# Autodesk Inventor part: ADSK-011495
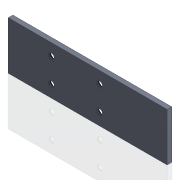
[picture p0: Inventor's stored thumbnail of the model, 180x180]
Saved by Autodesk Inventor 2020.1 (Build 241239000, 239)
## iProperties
Created: 2000-02
Part Number: ADSK-011495
Material: Pearson Stainless Steel
Description: PLT-04,FS,CP,01,065,019,VVVV,PLATE,FACE
Document SubType Name: Modeling
Designer: sspink
Density: 8.03 g/cm^3
Appearance: Pearson-Stainless
Mass: 307.028 g
Surface Area: 186.09 cm^2
Volume: 38.2351 cm^3
Control State: 0
Master: False
Checked Out: False
Shininess: 57.0
Length Units: 11269
Angle Units: 11279
Time Units: 11290
Mass Units: 11283
Length Display Precision: 3
Angle Display Precision: 2
Compacted: True
Cutlength: 6.5 *
Material Desc: FLAT,S/S,0.188 X 2.00
Material_number: A089267
Dimensions: 165x50x4,8 mm
Mass: 0,307 kg
Density: 8.03
Volumn: 38.29803755434586
Area: 188.2072000608875
PropertySet Name: Model Information
Author: sspink
Revision Number: -
Title: PLT-04,FS,CP,01,065,019,VVVV,PLATE,FACE
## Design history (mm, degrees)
node "Hole1" dims "d9" = 5.5, "d10" = 12.5, "d11" = 6.35, "d12" = 90 deg, "d13" = 19.05, "d14" = 118 deg, "d17" = 6
  sketch "Sketch2"
    geometry: L1 (82.5, 25)-(82.5, -25) reference; L2 (-82.5, -25)-(-82.5, 25) reference; L3 (-82.5, 0)-(82.5, 0); 4 further points
    constraints: 2 end point, 2 horizontal alignment, 2 midpoint, 2 vertical alignment
    dimensions: "d5" = 25 distance of point (-12.5, 12.7) point (-12.5, -12.3); "d7" = 50 distance of point (37.5, 12.7) point (-12.5, 12.7); "d15" = 45 distance from line of L1 point (37.5, 12.7); "d16" = 12.7 distance from line of point (-12.5, 12.7) L3
node "Solide1"
  node "Extrusion1" dims "d2" = 4.7625, "d3" = 0
sketch "Sketch1"
  geometry: L1 (-82.5, -25)-(82.5, -25); L2 (82.5, -25)-(82.5, 25); L3 (82.5, 25)-(-82.5, 25); L4 (-82.5, 25)-(-82.5, -25); 3 further points
  constraints: 8 end point, 2 midpoint, 2 parallel, 1 horizontal, 1 horizontal alignment, 1 perpendicular, 1 vertical alignment
  dimensions: "d0" = 50 distance between parallel lines of L1 L3; "d1" = 165 distance between parallel lines of L2 L4
node "Corps solides"
node "Corps surfaciques"
